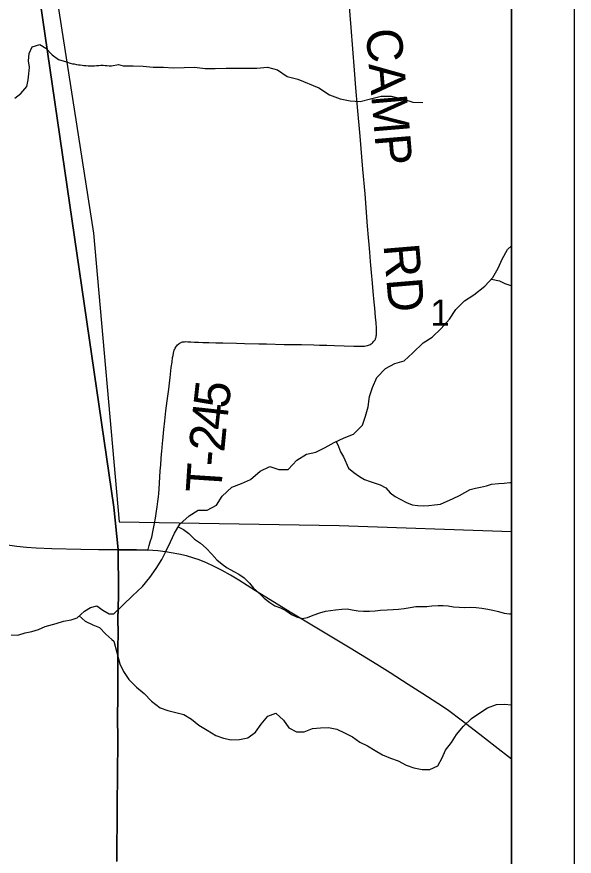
# Model space of a CAD drawing. Extents: x 0 to 34, y 0 to 22.
# Drawn here: x 8.111 to 9, y 15.371 to 16.71 of the extents above; entities that cross this region are included whole.
import ezdxf

# ---------------------------------------------------------------- set-up
doc = ezdxf.new("R2010")
doc.units = 0
for name, color, linetype in [('GM_X_Interstate_Route', 7, 'Continuous'), ('GM_X_Minor_River', 7, 'Continuous'), ('GM_X_Section_Text', 7, 'Continuous'), ('GM_X_State_Route', 7, 'Continuous'), ('GM_X_State_Shield', 7, 'Continuous'), ('GM_X_Township_Road', 7, 'Continuous'), ('GM_X_Township_Road_Text', 7, 'Continuous'), ('SH_Cut_Line', 7, 'Continuous'), ('SH_Data', 7, 'Continuous')]:
    doc.layers.add(name, color=color, linetype=linetype)

msp = doc.modelspace()

# ---------------------------------------------------------------- linework, layer by layer
at = {"layer": 'GM_X_Interstate_Route'}
for points in [[(8.1285, 16.8707), (8.2656, 15.9277), (8.2725, 15.8604), (8.2727, 15.8394), (8.2729, 15.8138), (8.2731, 15.7952), (8.2729, 15.7856), (8.2727, 15.7689), (8.2722, 15.748), (8.2723, 15.7286), (8.2722, 15.7017), (8.2722, 15.6789), (8.2722, 15.6512), (8.272, 15.6266), (8.2716, 15.592), (8.2718, 15.5581), (8.2714, 15.4987), (8.2711, 15.4552), (8.271, 15.4397), (8.2708, 15.4242), (8.2708, 15.4121), (8.2705, 15.4002), (8.2703, 15.3819), (8.2702, 15.3628)], [(8.2702, 15.3628), (8.2703, 15.3819), (8.2705, 15.4002), (8.2708, 15.4121), (8.2708, 15.4242), (8.271, 15.4397), (8.2711, 15.4552), (8.2714, 15.4987), (8.2718, 15.5581), (8.2716, 15.592), (8.272, 15.6266), (8.2722, 15.6512), (8.2722, 15.6789), (8.2722, 15.7017), (8.2723, 15.7286), (8.2722, 15.748), (8.2727, 15.7689), (8.2729, 15.7856), (8.2731, 15.7952), (8.2729, 15.8138), (8.2727, 15.8394), (8.2725, 15.8604), (8.2656, 15.9277), (8.1285, 16.8707)], [(8.9, 14.1), (8.9, 16.8746)]]:
    msp.add_lwpolyline(points, dxfattribs=at)
at = {"layer": 'GM_X_Minor_River'}
for points in [[(8.1078, 16.5806), (8.1173, 16.5881), (8.1269, 16.5994), (8.1289, 16.61), (8.1301, 16.6194), (8.1313, 16.6301), (8.1295, 16.6399), (8.1308, 16.6517), (8.1354, 16.6627), (8.1475, 16.6663), (8.1573, 16.6605), (8.1675, 16.6498), (8.1776, 16.6425), (8.1899, 16.6385)], [(8.1899, 16.6385), (8.1962, 16.6363), (8.1997, 16.6355), (8.2023, 16.6352), (8.2058, 16.6344), (8.2092, 16.634), (8.2118, 16.6336), (8.2153, 16.6332), (8.2179, 16.6328), (8.2213, 16.6328), (8.2248, 16.6324), (8.2316, 16.6324), (8.2347, 16.6324), (8.2381, 16.6328), (8.2415, 16.6328), (8.2449, 16.6332), (8.2484, 16.6332), (8.2518, 16.6328), (8.2544, 16.6328), (8.2582, 16.6324), (8.2617, 16.6324), (8.2733, 16.6341)], [(8.2733, 16.6341), (8.2807, 16.6323), (8.2967, 16.6321), (8.3126, 16.6315), (8.3286, 16.6301), (8.345, 16.6299), (8.3605, 16.6289), (8.378, 16.6295), (8.3944, 16.63), (8.4111, 16.6279), (8.4271, 16.6281), (8.445, 16.6286), (8.4606, 16.6284), (8.4773, 16.6285), (8.4937, 16.6287), (8.5108, 16.63), (8.5267, 16.6256), (8.5422, 16.6151), (8.5592, 16.6107), (8.5925, 16.5973), (8.6098, 16.5861), (8.6265, 16.5794), (8.6428, 16.5765), (8.6587, 16.5751), (8.6751, 16.5795), (8.6919, 16.5838), (8.7087, 16.584), (8.7261, 16.5796), (8.7424, 16.5744), (8.7587, 16.5738)], [(8.2657, 15.7576), (8.2956, 15.7862), (8.3114, 15.8016), (8.323, 15.8159), (8.3331, 15.8302), (8.3421, 15.8442), (8.3491, 15.8581), (8.3558, 15.8725), (8.3625, 15.8865), (8.3707, 15.9008), (8.3857, 15.914), (8.3999, 15.9233), (8.4147, 15.9231), (8.4293, 15.9309), (8.4382, 15.9456), (8.4537, 15.9598), (8.469, 15.9657), (8.4835, 15.972), (8.4993, 15.9855), (8.5142, 15.9929), (8.5286, 15.9881), (8.5438, 15.9883), (8.5573, 16.0029), (8.5727, 16.0126), (8.588, 16.0155), (8.6029, 16.0232), (8.6171, 16.031), (8.6332, 16.0384), (8.6477, 16.0443), (8.6624, 16.0586), (8.6671, 16.073), (8.6711, 16.0878), (8.6733, 16.1048), (8.6784, 16.1188), (8.6851, 16.1347), (8.699, 16.149), (8.7136, 16.1572), (8.7285, 16.1612), (8.7428, 16.1743), (8.759, 16.1904), (8.7735, 16.1993), (8.7878, 16.2129), (8.8013, 16.2279), (8.8114, 16.2433), (8.825, 16.2572), (8.8399, 16.2665), (8.8572, 16.2804), (8.87, 16.2943), (8.8786, 16.3094), (8.8849, 16.3238), (8.8935, 16.3392), (8.9, 16.345)], [(8.8679, 16.292), (8.8806, 16.2892), (8.8893, 16.2849), (8.8987, 16.2817), (8.9, 16.2819)], [(8.6205, 16.0326), (8.6242, 16.0245), (8.6271, 16.0161), (8.632, 16.008), (8.6401, 15.9904), (8.6483, 15.9831), (8.6574, 15.9769), (8.6657, 15.9722), (8.6744, 15.969), (8.6903, 15.9635), (8.6993, 15.9588), (8.7065, 15.9507), (8.7144, 15.9449), (8.7223, 15.9406), (8.7325, 15.9352), (8.7416, 15.9316), (8.7503, 15.9304), (8.7594, 15.9299), (8.7682, 15.9305), (8.7773, 15.9315), (8.7868, 15.9329), (8.8067, 15.9418), (8.8171, 15.9466), (8.8255, 15.9511), (8.8343, 15.9563), (8.8424, 15.9584), (8.8504, 15.9598), (8.8599, 15.962), (8.8683, 15.9646), (8.8794, 15.9659), (8.8885, 15.9662), (8.8973, 15.9672), (8.9, 15.9671)], [(8.3681, 15.8963), (8.377, 15.8924), (8.3853, 15.8858), (8.3943, 15.8769), (8.4041, 15.8707), (8.4131, 15.8626), (8.4221, 15.853), (8.4299, 15.8441), (8.4382, 15.8372), (8.4465, 15.831), (8.4571, 15.8251), (8.465, 15.8212), (8.4736, 15.8154), (8.4819, 15.8069), (8.4886, 15.7985), (8.4969, 15.7911), (8.5055, 15.783), (8.5145, 15.7757), (8.5224, 15.7703), (8.5315, 15.7675), (8.5402, 15.7628), (8.5489, 15.7566), (8.5572, 15.7531), (8.5663, 15.7503), (8.5747, 15.7517), (8.5838, 15.7554), (8.5942, 15.7594), (8.603, 15.762), (8.611, 15.763), (8.6193, 15.764), (8.6293, 15.7654), (8.638, 15.7657), (8.646, 15.764), (8.6555, 15.7624), (8.6638, 15.7619), (8.6733, 15.7618), (8.6825, 15.7624), (8.6912, 15.7634), (8.7015, 15.7641), (8.711, 15.7647), (8.7198, 15.765), (8.7289, 15.7664), (8.7385, 15.7681), (8.7472, 15.7692), (8.756, 15.7694), (8.7651, 15.7697), (8.7731, 15.7703), (8.783, 15.771), (8.791, 15.7712), (8.799, 15.7704), (8.8077, 15.7687), (8.8164, 15.7682), (8.8248, 15.7681), (8.8347, 15.7684), (8.8434, 15.7679), (8.8525, 15.7666), (8.862, 15.7653), (8.8704, 15.7637), (8.8791, 15.7617), (8.8882, 15.7589), (8.8969, 15.758), (8.9, 15.7577)], [(8.102, 15.7242), (8.1123, 15.7237), (8.1244, 15.7274), (8.1347, 15.7296), (8.1453, 15.7329), (8.1563, 15.7373), (8.1738, 15.7425), (8.1852, 15.7458), (8.1973, 15.7483), (8.2072, 15.7513), (8.2186, 15.7622), (8.2285, 15.7681), (8.2384, 15.7707), (8.2482, 15.7638), (8.258, 15.758), (8.2657, 15.7576)], [(8.2104, 15.7543), (8.22, 15.7458), (8.2321, 15.7404), (8.2426, 15.7361), (8.2528, 15.7254), (8.2625, 15.717), (8.2655, 15.7141)], [(8.2655, 15.7141), (8.2754, 15.6777), (8.2809, 15.6655), (8.2895, 15.6532), (8.3019, 15.6405), (8.3139, 15.6304), (8.3259, 15.6185), (8.3395, 15.608), (8.3516, 15.6033), (8.3773, 15.5969), (8.3894, 15.5899), (8.4014, 15.5802), (8.4143, 15.572), (8.4282, 15.5635), (8.4403, 15.5591), (8.4528, 15.5567), (8.4661, 15.5573), (8.4791, 15.5601), (8.4914, 15.5691), (8.5007, 15.5819), (8.5112, 15.5947), (8.5242, 15.5991), (8.5362, 15.5883), (8.5448, 15.576), (8.5568, 15.5694), (8.569, 15.5696), (8.5824, 15.5747), (8.5954, 15.5757), (8.6083, 15.5763), (8.6212, 15.5738), (8.6337, 15.568), (8.6461, 15.5613), (8.6582, 15.5532), (8.6703, 15.5473), (8.6823, 15.5399), (8.6944, 15.5329), (8.7072, 15.5274), (8.7194, 15.5231), (8.7322, 15.5161), (8.7443, 15.5121), (8.7576, 15.5096), (8.7697, 15.5095), (8.7824, 15.515), (8.7894, 15.5278), (8.7949, 15.5403), (8.8042, 15.5524), (8.8124, 15.5652), (8.8232, 15.5784), (8.8363, 15.5907), (8.8494, 15.5997), (8.8617, 15.6079), (8.8762, 15.613), (8.8888, 15.6136), (8.9, 15.6125)]]:
    msp.add_lwpolyline(points, dxfattribs=at)
at = {"layer": 'GM_X_State_Route'}
for points in [[(8.2727, 15.8599), (8.2412, 15.8597), (8.2132, 15.8604), (8.1666, 15.8617), (8.1418, 15.8624), (8.1263, 15.8635), (8.1109, 15.8652), (8.0925, 15.8679)], [(8.3198, 15.8591), (8.3016, 15.8597), (8.2727, 15.8599)], [(8.9, 15.5256), (8.8739, 15.5461), (8.8494, 15.5652), (8.8197, 15.5878), (8.7999, 15.6027), (8.7897, 15.6098), (8.7584, 15.63), (8.7349, 15.6451), (8.7062, 15.6637), (8.6852, 15.6768), (8.6427, 15.7027), (8.6189, 15.7173), (8.5896, 15.7349), (8.5471, 15.7606), (8.5152, 15.78), (8.4914, 15.7947), (8.4652, 15.8114), (8.4519, 15.8193), (8.4384, 15.8269), (8.4246, 15.834), (8.4134, 15.8392), (8.4019, 15.8437), (8.3932, 15.8467), (8.3813, 15.8501), (8.3692, 15.853), (8.357, 15.8553), (8.3479, 15.8567), (8.3356, 15.858), (8.3198, 15.8591)]]:
    msp.add_lwpolyline(points, dxfattribs=at)
at = {"layer": 'GM_X_State_Shield'}
msp.add_lwpolyline([(8.9, 15.8892), (8.9, 16.8787), (8.1545, 16.8705), (8.2333, 16.3651), (8.2739, 15.9045), (8.6253, 15.8989)], close=True, dxfattribs=at)
at = {"layer": 'GM_X_Township_Road'}
for points in [[(8.3198, 15.8591), (8.3203, 15.8606), (8.3222, 15.8668), (8.3238, 15.8724), (8.326, 15.8802), (8.3284, 15.8911), (8.3306, 15.902), (8.3322, 15.9105), (8.3339, 15.9218), (8.3349, 15.9285), (8.336, 15.9372), (8.3367, 15.9442), (8.3372, 15.9498), (8.3377, 15.9568), (8.3397, 15.986), (8.3404, 15.9957), (8.3411, 16.0054), (8.3416, 16.0126), (8.342, 16.0175), (8.3425, 16.0228), (8.3432, 16.0302), (8.3437, 16.0343), (8.3443, 16.0404), (8.3455, 16.0517), (8.3469, 16.0656), (8.3488, 16.0814), (8.3508, 16.0977), (8.3531, 16.1165), (8.3542, 16.1257), (8.3553, 16.1347), (8.356, 16.1402), (8.3573, 16.1509), (8.3584, 16.1593), (8.3594, 16.1667), (8.36, 16.1699), (8.3607, 16.1736), (8.3613, 16.1762), (8.3621, 16.1785), (8.3628, 16.18), (8.3637, 16.1819), (8.3644, 16.1834), (8.3653, 16.1846), (8.3659, 16.1856), (8.3674, 16.1871), (8.3687, 16.1882), (8.3699, 16.1892), (8.3716, 16.1902), (8.3728, 16.1908), (8.3738, 16.1912), (8.3753, 16.1916), (8.3763, 16.1918), (8.3773, 16.192), (8.3784, 16.192), (8.3806, 16.1921), (8.3835, 16.192), (8.3883, 16.1917), (8.3945, 16.1913), (8.4006, 16.1912), (8.4077, 16.1909), (8.4169, 16.1907), (8.4283, 16.1903), (8.4396, 16.19), (8.4614, 16.1895), (8.474, 16.1892), (8.4968, 16.1886), (8.5089, 16.1884), (8.5372, 16.1877), (8.5651, 16.1873), (8.5846, 16.1868), (8.5935, 16.1866), (8.6053, 16.1863), (8.6178, 16.1859), (8.6328, 16.1853), (8.6483, 16.1848), (8.6547, 16.1846), (8.6581, 16.1846), (8.6629, 16.1848), (8.6655, 16.1851), (8.6675, 16.1853), (8.6702, 16.1859), (8.6717, 16.1864), (8.6735, 16.187), (8.6749, 16.1877), (8.6763, 16.1886), (8.6776, 16.1895), (8.679, 16.1908), (8.6806, 16.1927), (8.6823, 16.1951), (8.6828, 16.196), (8.6832, 16.1969), (8.6837, 16.1982), (8.684, 16.1991), (8.6843, 16.2012), (8.6845, 16.2031), (8.6847, 16.2056), (8.6847, 16.2095), (8.6845, 16.2134), (8.6839, 16.2223), (8.6831, 16.2309), (8.6817, 16.2454), (8.6809, 16.2551), (8.6794, 16.272), (8.6781, 16.2853), (8.6765, 16.3022), (8.6751, 16.3198), (8.6738, 16.3349), (8.6728, 16.3469), (8.6718, 16.3583), (8.6704, 16.3762), (8.6664, 16.4277), (8.663, 16.4674), (8.6584, 16.52), (8.6544, 16.5664), (8.6518, 16.5973), (8.6494, 16.6251), (8.644, 16.6932), (8.6392, 16.7528)], [(8.2704, 15.3623), (8.2706, 15.3813), (8.2707, 15.3996), (8.271, 15.4116), (8.2711, 15.4236), (8.2712, 15.4391), (8.2713, 15.4547), (8.2716, 15.4981), (8.272, 15.5575), (8.2718, 15.5915), (8.2722, 15.626), (8.2724, 15.6507), (8.2724, 15.6784), (8.2724, 15.7011), (8.2725, 15.7281), (8.2724, 15.7475), (8.2729, 15.7684), (8.2731, 15.785), (8.2733, 15.7947), (8.2731, 15.8133), (8.2729, 15.8389), (8.2727, 15.8599)], [(8.2727, 15.8599), (8.3016, 15.8597), (8.3198, 15.8591)]]:
    msp.add_lwpolyline(points, dxfattribs=at)
at = {"layer": 'SH_Cut_Line'}
for points in [[(8.9, 14.1), (8.9, 20.9)], [(8.1285, 16.8707), (8.2656, 15.9277), (8.2725, 15.8604), (8.2727, 15.8394), (8.2729, 15.8138), (8.2731, 15.7952), (8.2729, 15.7856), (8.2727, 15.7689), (8.2722, 15.748), (8.2723, 15.7286), (8.2722, 15.7017), (8.2722, 15.6789), (8.2722, 15.6512), (8.272, 15.6266), (8.2716, 15.592), (8.2718, 15.5581), (8.2714, 15.4987), (8.2711, 15.4552), (8.271, 15.4397), (8.2708, 15.4242), (8.2708, 15.4121), (8.2705, 15.4002), (8.2703, 15.3819), (8.2702, 15.3628)], [(8.2702, 15.3628), (8.2703, 15.3819), (8.2705, 15.4002), (8.2708, 15.4121), (8.2708, 15.4242), (8.271, 15.4397), (8.2711, 15.4552), (8.2714, 15.4987), (8.2718, 15.5581), (8.2716, 15.592), (8.272, 15.6266), (8.2722, 15.6512), (8.2722, 15.6789), (8.2722, 15.7017), (8.2723, 15.7286), (8.2722, 15.748), (8.2727, 15.7689), (8.2729, 15.7856), (8.2731, 15.7952), (8.2729, 15.8138), (8.2727, 15.8394), (8.2725, 15.8604), (8.2656, 15.9277), (8.1285, 16.8707)]]:
    msp.add_lwpolyline(points, dxfattribs=at)
at = {"layer": 'SH_Data'}
for p, q in [((9, 21), (9, 14)), ((8.9, 20.9), (8.9, 14.1))]:
    msp.add_line(p, q, dxfattribs=at)

# ---------------------------------------------------------------- texts
at = {"layer": 'GM_X_Section_Text'}
msp.add_text('1', height=0.0419, rotation=0, dxfattribs=at).set_placement((8.7705, 16.2174))
at = {"layer": 'GM_X_Township_Road_Text'}
for s, height, rotation, p in [('CAMP', 0.05682, 274.8, (8.6674, 16.6898)), ('RD', 0.05682, 274.8038, (8.6957, 16.3465)), ('5', 0.0568, 83.5702, (8.4487, 16.0841)), ('4', 0.0568, 83.7767, (8.4449, 16.0494)), ('2', 0.0568, 84.4623, (8.4416, 16.0147)), ('-', 0.0568, 85.1858, (8.4396, 15.9916)), ('T', 0.0568, 86.2432, (8.4369, 15.9495))]:
    msp.add_text(s, height=height, rotation=rotation, dxfattribs=at).set_placement(p)

doc.saveas('drawing.dxf')
